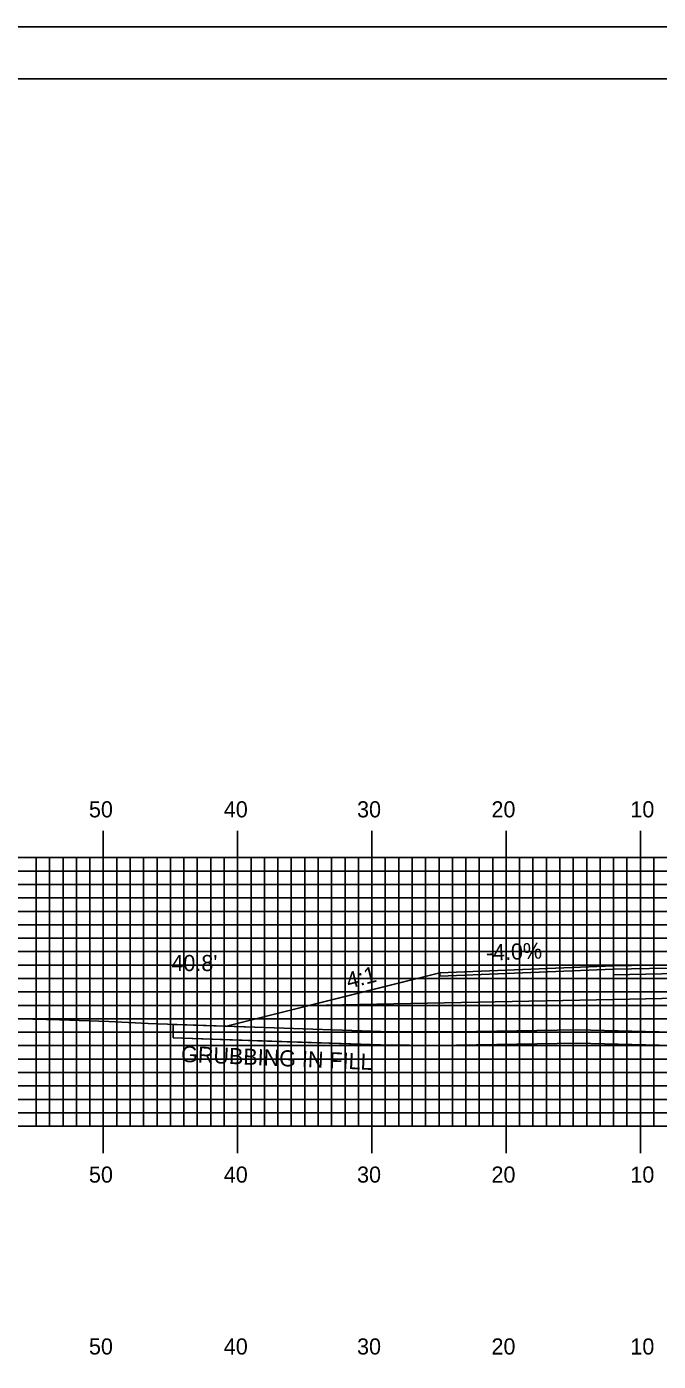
# Model space of a CAD drawing. Extents: x 1773203 to 1773546, y 442591 to 442811.
# Drawn here: x 1773312.9 to 1773360, y 442711.2 to 442810.5 of the extents above; entities that cross this region are included whole.
import ezdxf

# ---------------------------------------------------------------- set-up
doc = ezdxf.new("R2010")
doc.units = 0
for name, color, linetype in [('ANNOTATION', 7, 'Continuous'), ('BORDER', 7, 'Continuous'), ('D_Drainage_Culvert', 7, 'Continuous'), ('D_Roadway_Centerline', 7, 'Continuous'), ('D_Roadway_Edge_Shoulder', 7, 'Continuous'), ('D_Roadway_Edge_TW', 7, 'Continuous'), ('D_Roadway_Pavement', 7, 'Continuous'), ('D_Roadway_SubGrade', 7, 'Continuous'), ('D_Text_Standard', 7, 'Continuous'), ('GRUBBING IN FILL', 7, 'Continuous'), ('H_V ANNOTATION', 7, 'Continuous'), ('MAJOR', 7, 'Continuous'), ('MINOR', 7, 'Continuous'), ('PLOT BOUNDARY', 7, 'Continuous'), ('S_Roadway_Centerline', 7, 'Continuous')]:
    doc.layers.add(name, color=color, linetype=linetype)

msp = doc.modelspace()

# ---------------------------------------------------------------- linework, layer by layer
at = {"layer": 'BORDER'}
msp.add_lwpolyline([(1773219.033, 442596.665), (1773539.033, 442596.665), (1773539.033, 442806.665), (1773219.033, 442806.665)], close=True, dxfattribs=at)
at = {"layer": 'D_Drainage_Culvert'}
msp.add_line((1773356.632, 442740.604), (1773343.707, 442740.087), dxfattribs=at)
msp.add_lwpolyline([(1773343.707, 442740.087), (1773339.707, 442739.087), (1773327.807, 442736.112)], dxfattribs=at)
at = {"layer": 'D_Roadway_Centerline'}
msp.add_lwpolyline([(1773327.807, 442736.112), (1773343.707, 442740.087), (1773348.633, 442740.284), (1773356.633, 442740.604), (1773368.632, 442740.844), (1773371.168, 442740.793), (1773380.633, 442740.604), (1773388.633, 442740.284), (1773388.633, 442740.284), (1773398.809, 442737.74), (1773411.388, 442734.596)], dxfattribs=at)
at = {"layer": 'D_Roadway_Edge_Shoulder'}
msp.add_lwpolyline([(1773356.632, 442740.604), (1773348.633, 442740.284), (1773348.633, 442740.034), (1773356.632, 442740.354)], close=True, dxfattribs=at)
at = {"layer": 'D_Roadway_Edge_TW'}
msp.add_lwpolyline([(1773356.632, 442740.354), (1773356.632, 442740.604), (1773368.632, 442740.844), (1773380.633, 442740.604), (1773380.633, 442740.354), (1773368.632, 442740.594)], close=True, dxfattribs=at)
at = {"layer": 'D_Roadway_Pavement'}
msp.add_lwpolyline([(1773356.632, 442739.937), (1773356.632, 442740.354), (1773368.632, 442740.594), (1773380.633, 442740.354), (1773380.633, 442739.937), (1773368.632, 442740.177)], close=True, dxfattribs=at)
at = {"layer": 'D_Roadway_SubGrade'}
msp.add_lwpolyline([(1773356.632, 442738.104), (1773333.959, 442737.65), (1773343.707, 442740.087), (1773343.707, 442739.829), (1773348.633, 442740.034), (1773356.632, 442740.354), (1773368.632, 442740.594), (1773380.633, 442740.354), (1773388.633, 442740.034), (1773388.633, 442740.034), (1773388.633, 442740.284), (1773398.809, 442737.74), (1773380.633, 442738.104), (1773368.632, 442738.344)], close=True, dxfattribs=at)
at = {"layer": 'GRUBBING IN FILL'}
msp.add_line((1773323.846, 442736.25), (1773323.846, 442735.249), dxfattribs=at)
msp.add_line((1773323.846, 442736.25), (1773323.846, 442735.249), dxfattribs=at)
msp.add_lwpolyline([(1773323.846, 442736.25), (1773330.638, 442736.014), (1773339.301, 442735.713), (1773344.935, 442735.692), (1773349.428, 442735.77), (1773353.921, 442735.847), (1773360.04, 442735.698), (1773366.16, 442735.55), (1773368.633, 442735.449), (1773368.633, 442734.448), (1773366.13, 442734.55), (1773360.023, 442734.698), (1773353.917, 442734.846), (1773349.433, 442734.769), (1773343.621, 442734.682), (1773339.276, 442734.714), (1773331.561, 442734.981), (1773323.846, 442735.249)], close=True, dxfattribs=at)
msp.add_lwpolyline([(1773323.846, 442736.25), (1773330.638, 442736.014), (1773339.301, 442735.713), (1773344.935, 442735.692), (1773349.428, 442735.77), (1773353.921, 442735.847), (1773360.04, 442735.698), (1773366.16, 442735.55), (1773368.633, 442735.449), (1773368.633, 442734.448), (1773366.13, 442734.55), (1773360.023, 442734.698), (1773353.917, 442734.846), (1773349.433, 442734.769), (1773343.621, 442734.682), (1773339.276, 442734.714), (1773331.561, 442734.981), (1773323.846, 442735.249)], close=True, dxfattribs=at)
msp.add_lwpolyline([(1773323.846, 442735.249), (1773339.276, 442734.714), (1773342.295, 442734.671), (1773344.948, 442734.693), (1773353.917, 442734.846), (1773366.13, 442734.55), (1773367.217, 442734.51), (1773372.878, 442734.265), (1773387.414, 442733.652), (1773390.302, 442733.534), (1773409.6, 442733.56), (1773413.419, 442733.636)], dxfattribs=at)
msp.add_lwpolyline([(1773323.846, 442735.249), (1773339.276, 442734.714), (1773342.295, 442734.671), (1773344.948, 442734.693), (1773353.917, 442734.846), (1773366.13, 442734.55), (1773367.217, 442734.51), (1773372.878, 442734.265), (1773387.414, 442733.652), (1773390.302, 442733.534), (1773409.6, 442733.56), (1773413.419, 442733.636)], dxfattribs=at)
at = {"layer": 'MAJOR'}
for p, q in [((1773318.633, 442750.669), (1773318.633, 442748.665)), ((1773328.633, 442750.669), (1773328.633, 442748.665)), ((1773338.633, 442750.669), (1773338.633, 442748.665)), ((1773348.633, 442750.669), (1773348.633, 442748.665)), ((1773358.633, 442750.669), (1773358.633, 442748.665)), ((1773228.633, 442748.665), (1773508.633, 442748.665)), ((1773228.633, 442748.665), (1773508.633, 442748.665)), ((1773318.633, 442728.665), (1773318.633, 442748.665)), ((1773328.633, 442728.665), (1773328.633, 442748.665)), ((1773338.633, 442728.665), (1773338.633, 442748.665)), ((1773348.633, 442728.665), (1773348.633, 442748.665)), ((1773358.633, 442728.665), (1773358.633, 442748.665)), ((1773228.633, 442743.665), (1773508.633, 442743.665)), ((1773228.633, 442738.665), (1773508.633, 442738.665)), ((1773228.633, 442733.665), (1773508.633, 442733.665)), ((1773228.633, 442728.665), (1773508.633, 442728.665)), ((1773228.633, 442728.665), (1773508.633, 442728.665)), ((1773318.633, 442726.661), (1773318.633, 442728.665)), ((1773328.633, 442726.661), (1773328.633, 442728.665)), ((1773338.633, 442726.661), (1773338.633, 442728.665)), ((1773348.633, 442726.661), (1773348.633, 442728.665)), ((1773358.633, 442726.661), (1773358.633, 442728.665))]:
    msp.add_line(p, q, dxfattribs=at)
at = {"layer": 'MINOR'}
for p, q in [((1773313.633, 442728.665), (1773313.633, 442748.665)), ((1773314.633, 442728.665), (1773314.633, 442748.665)), ((1773315.633, 442728.665), (1773315.633, 442748.665)), ((1773316.633, 442728.665), (1773316.633, 442748.665)), ((1773317.633, 442728.665), (1773317.633, 442748.665)), ((1773319.633, 442728.665), (1773319.633, 442748.665)), ((1773320.633, 442728.665), (1773320.633, 442748.665)), ((1773321.633, 442728.665), (1773321.633, 442748.665)), ((1773322.633, 442728.665), (1773322.633, 442748.665)), ((1773323.633, 442728.665), (1773323.633, 442748.665)), ((1773324.633, 442728.665), (1773324.633, 442748.665)), ((1773325.633, 442728.665), (1773325.633, 442748.665)), ((1773326.633, 442728.665), (1773326.633, 442748.665)), ((1773327.633, 442728.665), (1773327.633, 442748.665)), ((1773329.633, 442728.665), (1773329.633, 442748.665)), ((1773330.633, 442728.665), (1773330.633, 442748.665)), ((1773331.633, 442728.665), (1773331.633, 442748.665)), ((1773332.633, 442728.665), (1773332.633, 442748.665)), ((1773333.633, 442728.665), (1773333.633, 442748.665)), ((1773334.633, 442728.665), (1773334.633, 442748.665)), ((1773335.633, 442728.665), (1773335.633, 442748.665)), ((1773336.633, 442728.665), (1773336.633, 442748.665)), ((1773337.633, 442728.665), (1773337.633, 442748.665)), ((1773339.633, 442728.665), (1773339.633, 442748.665)), ((1773340.633, 442728.665), (1773340.633, 442748.665)), ((1773341.633, 442728.665), (1773341.633, 442748.665)), ((1773342.633, 442728.665), (1773342.633, 442748.665)), ((1773343.633, 442728.665), (1773343.633, 442748.665)), ((1773344.633, 442728.665), (1773344.633, 442748.665)), ((1773345.633, 442728.665), (1773345.633, 442748.665)), ((1773346.633, 442728.665), (1773346.633, 442748.665)), ((1773347.633, 442728.665), (1773347.633, 442748.665)), ((1773349.633, 442728.665), (1773349.633, 442748.665)), ((1773350.633, 442728.665), (1773350.633, 442748.665)), ((1773351.633, 442728.665), (1773351.633, 442748.665)), ((1773352.633, 442728.665), (1773352.633, 442748.665)), ((1773353.633, 442728.665), (1773353.633, 442748.665)), ((1773354.633, 442728.665), (1773354.633, 442748.665)), ((1773355.633, 442728.665), (1773355.633, 442748.665)), ((1773356.633, 442728.665), (1773356.633, 442748.665)), ((1773357.633, 442728.665), (1773357.633, 442748.665)), ((1773359.633, 442728.665), (1773359.633, 442748.665)), ((1773228.633, 442747.665), (1773508.633, 442747.665)), ((1773228.633, 442746.665), (1773508.633, 442746.665)), ((1773228.633, 442745.665), (1773508.633, 442745.665)), ((1773228.633, 442744.665), (1773508.633, 442744.665)), ((1773228.633, 442742.665), (1773508.633, 442742.665)), ((1773228.633, 442741.665), (1773508.633, 442741.665)), ((1773228.633, 442740.665), (1773508.633, 442740.665)), ((1773228.633, 442739.665), (1773508.633, 442739.665)), ((1773228.633, 442737.665), (1773508.633, 442737.665)), ((1773228.633, 442736.665), (1773508.633, 442736.665)), ((1773228.633, 442735.665), (1773508.633, 442735.665)), ((1773228.633, 442734.665), (1773508.633, 442734.665)), ((1773228.633, 442732.665), (1773508.633, 442732.665)), ((1773228.633, 442731.665), (1773508.633, 442731.665)), ((1773228.633, 442730.665), (1773508.633, 442730.665)), ((1773228.633, 442729.665), (1773508.633, 442729.665))]:
    msp.add_line(p, q, dxfattribs=at)
at = {"layer": 'PLOT BOUNDARY'}
msp.add_lwpolyline([(1773202.846, 442590.547), (1773542.846, 442590.547), (1773542.846, 442810.547), (1773202.846, 442810.547)], close=True, dxfattribs=at)
at = {"layer": 'S_Roadway_Centerline'}
msp.add_lwpolyline([(1773300.463, 442736.972), (1773315.371, 442736.594), (1773319.046, 442736.474), (1773321.975, 442736.315), (1773339.301, 442735.713), (1773342.298, 442735.671), (1773344.935, 442735.692), (1773353.921, 442735.847), (1773366.16, 442735.55), (1773367.257, 442735.509), (1773372.921, 442735.264), (1773387.455, 442734.651), (1773390.322, 442734.534), (1773409.589, 442734.56), (1773414.673, 442734.661), (1773430.964, 442734.646)], dxfattribs=at)

# ---------------------------------------------------------------- texts
at = {"layer": 'ANNOTATION'}
for s, rotation, p in [('-4.0%', 2.29073, (1773347.143, 442740.984)), ('4:1', 14.04242, (1773336.895, 442738.901))]:
    msp.add_text(s, height=1.2, rotation=rotation, dxfattribs=at).set_placement(p)
at = {"layer": 'D_Text_Standard'}
msp.add_text("40.8'", height=1.2, dxfattribs=at).set_placement((1773323.7, 442740.219))
at = {"layer": 'GRUBBING IN FILL'}
msp.add_text('GRUBBING IN FILL', height=1.2, rotation=357.57187, dxfattribs=at).set_placement((1773324.404, 442733.456))
at = {"layer": 'H_V ANNOTATION'}
for s, p in [('50', (1773317.562, 442751.665)), ('40', (1773327.605, 442751.665)), ('30', (1773337.53, 442751.665)), ('20', (1773347.541, 442751.665)), ('10', (1773357.884, 442751.665)), ('50', (1773317.562, 442724.465)), ('40', (1773327.605, 442724.465)), ('30', (1773337.53, 442724.465)), ('20', (1773347.541, 442724.465)), ('10', (1773357.884, 442724.465)), ('50', (1773317.562, 442711.665)), ('40', (1773327.605, 442711.665)), ('30', (1773337.53, 442711.665)), ('20', (1773347.541, 442711.665)), ('10', (1773357.884, 442711.665))]:
    msp.add_text(s, height=1.2, dxfattribs=at).set_placement(p)

doc.saveas('drawing.dxf')
